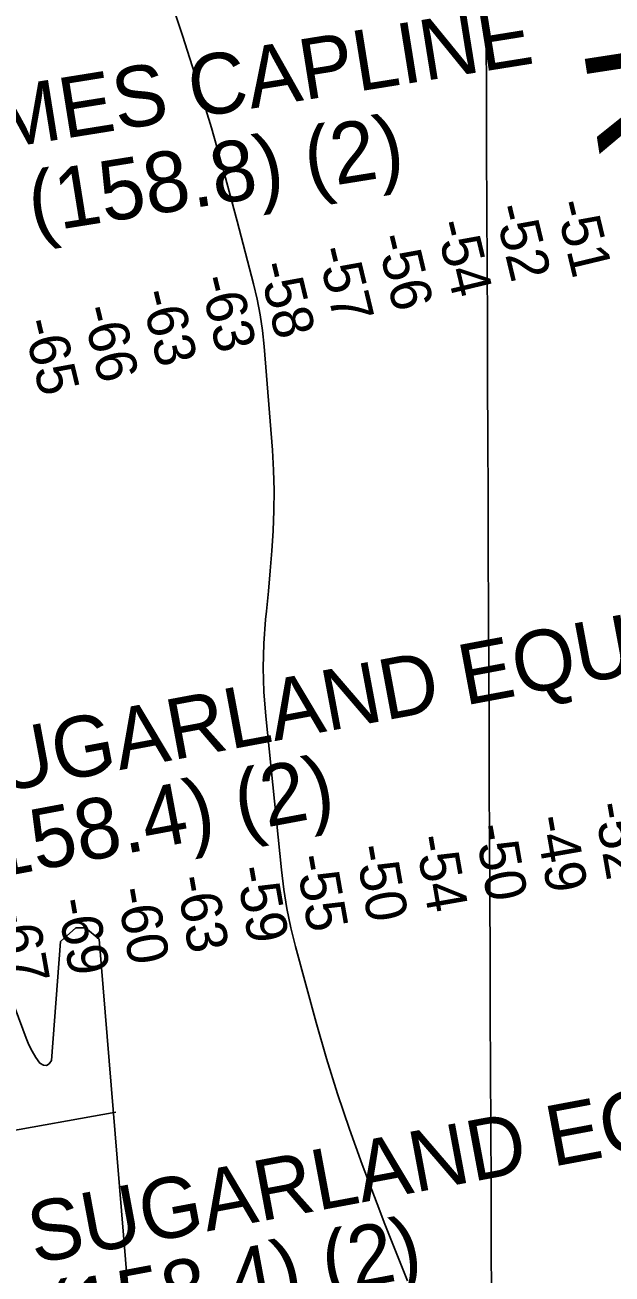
# Model space of a CAD drawing. Extents: x 3419139 to 3457078, y 540382 to 565875.
# Drawn here: x 3438316 to 3439284, y 548818 to 550877 of the extents above; entities that cross this region are included whole.
import ezdxf

# ---------------------------------------------------------------- set-up
doc = ezdxf.new("R2010")
doc.units = 0
for name, color, linetype in [('V-CHAN-NAID', 7, 'Continuous'), ('V-GRID-MAJR', 7, 'Continuous'), ('V-RIVR-IDEN', 7, 'Continuous'), ('V-RIVR-RANG', 7, 'Continuous'), ('V-TOPO-MINR', 7, 'Continuous')]:
    doc.layers.add(name, color=color, linetype=linetype)

msp = doc.modelspace()

# ---------------------------------------------------------------- linework, layer by layer
at = {"layer": 'V-GRID-MAJR'}
msp.add_spline([(3439098.8, 545841.1), (3439072.3, 551898.7), (3439045.9, 557959.6), (3439019.4, 564020.6), (3439019.4, 564024.1)], degree=3, dxfattribs=at)
at = {"layer": 'V-RIVR-RANG'}
msp.add_line((3437481.3, 548909.5), (3438465.8, 549084.5), dxfattribs=at)
at = {"layer": 'V-TOPO-MINR'}
for points in [[(3438946.7, 548806.4), (3438939.3, 548825.7), (3438931.6, 548844.9), (3438923.8, 548864.1), (3438916.1, 548883.3), (3438908.5, 548902.6), (3438901.1, 548921.9), (3438872.2, 548998.4), (3438851.3, 549056.3), (3438831.5, 549114.6), (3438813.3, 549173.3), (3438796.3, 549232.5), (3438762.3, 549357.5), (3438754.6, 549388.8), (3438747.9, 549420.2), (3438742.8, 549452), (3438738.8, 549483.9), (3438712.9, 549737.5), (3438710.1, 549777.4), (3438708.8, 549817.3), (3438710, 549857.2), (3438712.8, 549897.1), (3438714.2, 549910.7), (3438717.4, 549943.8), (3438720.3, 549977), (3438722.9, 550010.1), (3438725.2, 550043.4), (3438726.6, 550076.6), (3438727, 550109.8), (3438726, 550143), (3438724.1, 550176.2), (3438710.3, 550347), (3438707.5, 550373.2), (3438703.8, 550399.1), (3438698.8, 550424.9), (3438692.8, 550450.5), (3438666, 550554), (3438645.2, 550631.1), (3438623.4, 550707.8), (3438600, 550784), (3438575.5, 550860), (3438528.4, 551001.1)], [(3438501.2, 548601), (3438438.1, 549369.6), (3438415.8, 549388.6), (3438399.9, 549388.5), (3438374.5, 549366.1), (3438359.6, 549169.8), (3438355.8, 549164.4), (3438351.5, 549161.4), (3438346.3, 549162.1), (3438340.5, 549165.3), (3438333.8, 549175), (3438327.6, 549185.1), (3438322.3, 549195.6), (3438317.7, 549206.5), (3438286.9, 549289.8)]]:
    msp.add_lwpolyline(points, dxfattribs=at)

# ---------------------------------------------------------------- texts
at = {"layer": 'V-CHAN-NAID'}
for s, rotation, p in [('ST JAMES CAPLINE', 9.1127, (3437911, 550614.3)), ('NO. 1 (158.8) (2)', 9.1127, (3437947.7, 550471.7)), ('SUGARLAND EQULION NO. 1 ', 10.5984, (3438186.9, 549595.1)), ('(158.4) (2)', 10.5984, (3438217.7, 549461.2)), ('SUGARLAND EQULION NO. 1 ', 10.5984, (3438331.2, 548834.5)), ('(158.4) (2)', 10.5984, (3438362, 548700.6))]:
    msp.add_text(s, height=100, rotation=rotation, dxfattribs=at).set_placement(p)
at = {"layer": 'V-RIVR-IDEN'}
msp.add_text('R', height=200, rotation=278.779, dxfattribs=at).set_placement((3439236, 550842.9))
at = {"layer": 'V-RIVR-RANG'}
for s, rotation, p in [('-51', 283.5449, (3439190.3, 550583.2)), ('-52', 283.5449, (3439089.2, 550576.2)), ('-54', 283.5449, (3438992.6, 550550.1)), ('-56', 283.5449, (3438895.2, 550527.2)), ('-57', 283.5449, (3438797.3, 550506.6)), ('-58', 283.5449, (3438700.6, 550481.4)), ('-63', 283.5449, (3438603.2, 550458.7)), ('-63', 283.5449, (3438505.9, 550435.5)), ('-66', 283.5449, (3438409.3, 550409.3)), ('-65', 283.5449, (3438311.7, 550387.6)), ('-52', 279.9599, (3439254.2, 549592.1)), ('-50', 279.9599, (3439057.4, 549556.1)), ('-49', 279.9599, (3439156.5, 549570.1)), ('-54', 279.9599, (3438959.1, 549538)), ('-50', 279.9599, (3438860.4, 549522)), ('-55', 279.9599, (3438761.7, 549505.8)), ('-59', 279.9599, (3438663.5, 549486.9)), ('-60', 279.9599, (3438466.6, 549451.7)), ('-63', 279.9599, (3438564.7, 549471.1)), ('-69', 279.9599, (3438368.2, 549433.6)), ('-67', 279.9599, (3438269.2, 549419.4))]:
    msp.add_text(s, height=67, rotation=rotation, dxfattribs=at).set_placement(p)

doc.saveas('drawing.dxf')
